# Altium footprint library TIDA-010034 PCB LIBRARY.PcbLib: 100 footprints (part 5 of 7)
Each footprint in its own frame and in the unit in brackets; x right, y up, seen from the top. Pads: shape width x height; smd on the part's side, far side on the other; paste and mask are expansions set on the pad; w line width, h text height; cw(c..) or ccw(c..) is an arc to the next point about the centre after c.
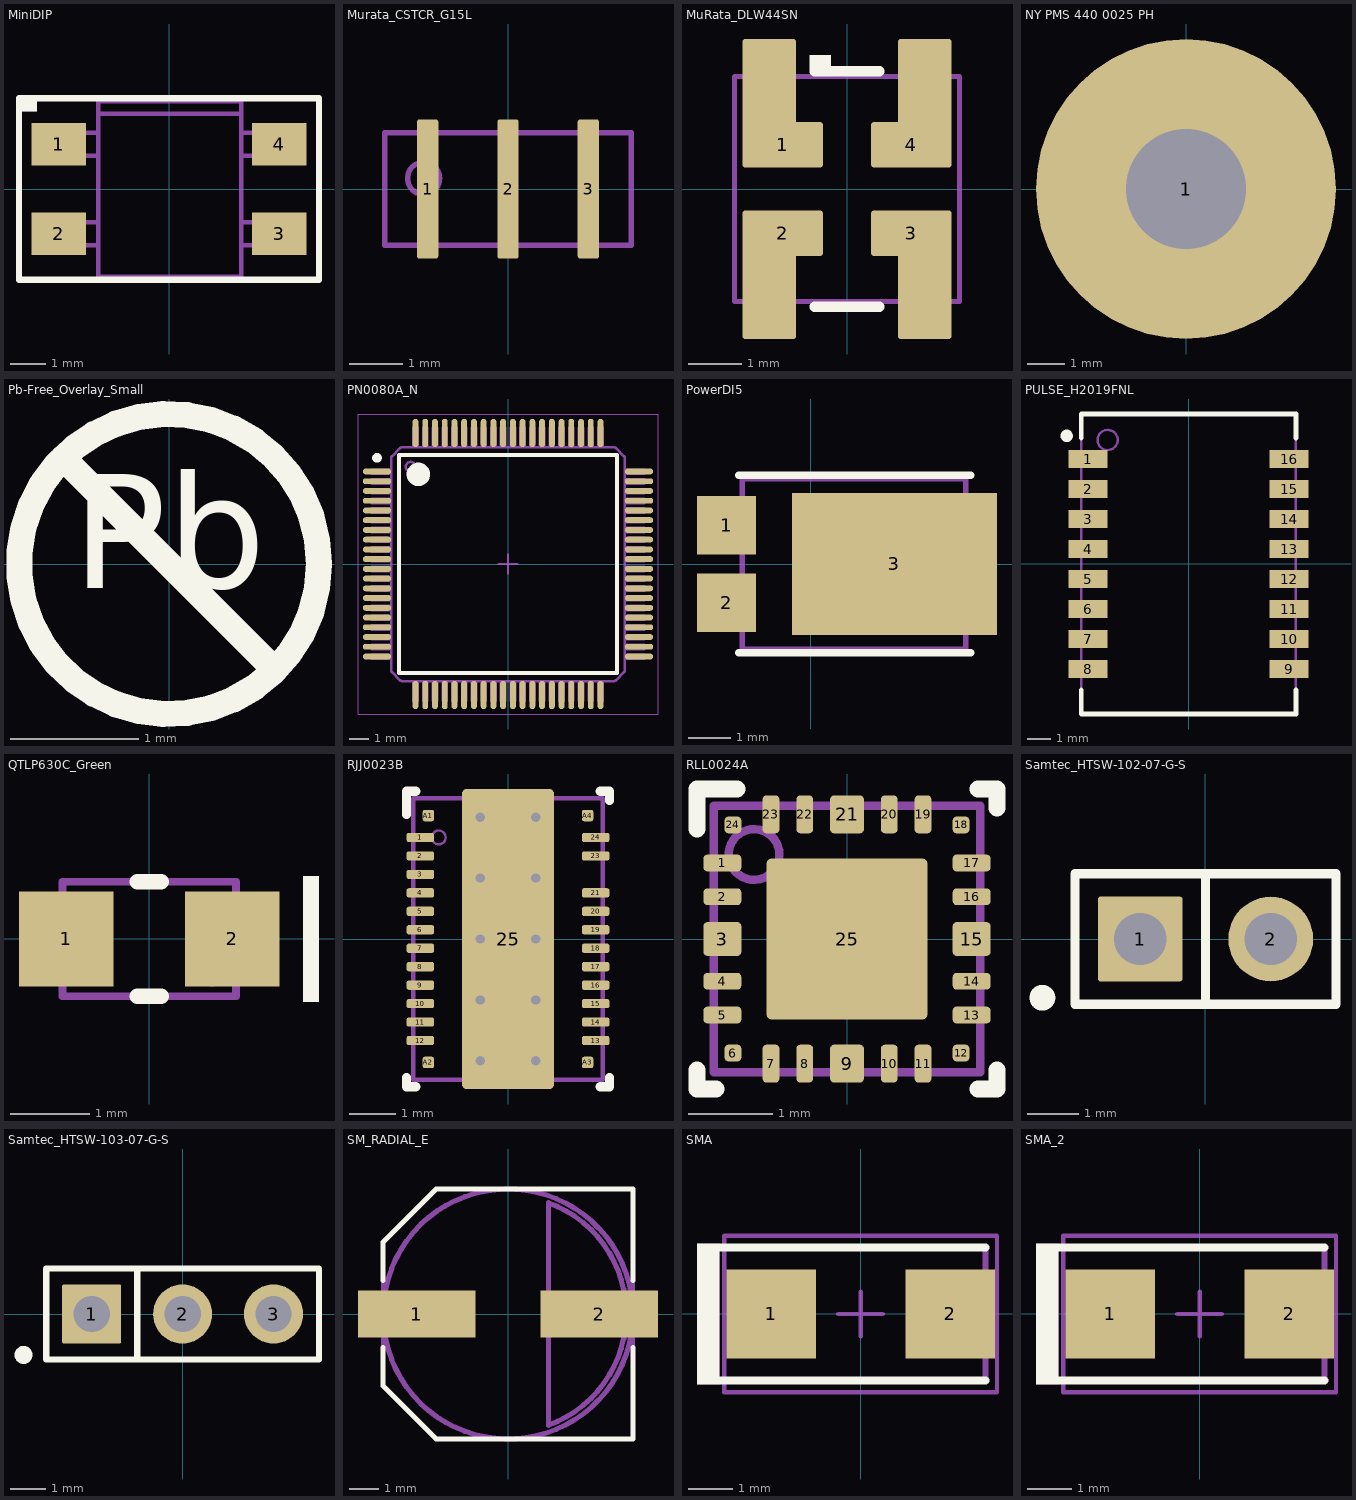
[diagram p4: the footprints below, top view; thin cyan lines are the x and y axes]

## MiniDIP [mm] "Land pattern created based on STEP model."
height 2.7
pads (4):
  rect 1.52x1.2 smd: 1(-3.075,1.25) 2(-3.075,-1.25) 3(3.075,-1.25) 4(3.075,1.25)
Top Overlay:
  rectangle: -4.191,2.159 -3.683,2.54
  lines w0.178: -4.191,-2.54 0,-2.54 4.191,-2.54 4.191,0 4.191,2.54 0,2.54 -4.191,2.54 -4.191,0 -4.191,-2.54
Mechanical 5:
  rectangle: -4.191,2.159 -3.683,2.54
  lines w0.127: -1.975,-1.575 -2.825,-1.575 ; -1.975,-0.925 -2.825,-0.925 ; -1.975,0.925 -2.825,0.925 ; -1.975,1.575 -2.825,1.575 ; 2.025,-1.575 2.875,-1.575 ; 2.025,-0.925 2.875,-0.925 ; 2.025,0.925 2.875,0.925 ; 2.025,1.575 2.875,1.575 ; -2.825,-1.575 -2.825,-0.925 ; -2.825,-1.575 -3.475,-1.575 -3.475,-0.925 -2.825,-0.925 ; -2.825,0.925 -3.475,0.925 -3.475,1.575 -2.825,1.575 ; -2.825,0.925 -2.825,1.575 ; -1.975,2.1 2.025,2.1 ; -1.975,2.1 -1.975,2.45 2.025,2.45 2.025,2.1 ; -1.975,2.1 -1.975,-2.45 2.025,-2.45 2.025,2.1 ; 2.875,-1.575 3.525,-1.575 3.525,-0.925 2.875,-0.925 ; 2.875,-1.575 2.875,-0.925 ; 2.875,0.925 3.525,0.925 3.525,1.575 2.875,1.575 ; 2.875,0.925 2.875,1.575
  text ".Designator" at -1.675,-0.25 h0.76
3D body "Minidip.stp": height 2.75, standoff 0, extent -3.5,-2.45 3.5,2.45

## Murata_CSTCR_G15L [mm] "Murata"
height 1.15
pads (3):
  rrect25% 0.4x2.6 smd: 1(-1.5,0) 2(0,0) 3(1.5,0)
Mechanical 5:
  circle w0.1: c-1.575,0.2 r0.3
  lines w0.1: -2.3,-1.05 -2.3,1.05 2.3,1.05 2.3,-1.05 -2.3,-1.05
  text ".Designator" at -0.95,-0.325 h0.51
3D body: height 0.6, standoff 0, extent -2.299,-1.049 2.299,1.051
3D body: height 1.2, standoff 0.6, extent -2,-0.875 2,0.875

## MuRata_DLW44SN [mm] "SMD, 4-Leads, Body 4.2x4.2mm"
height 1.5
pads (8):
  rrect12% 1.5x0.85 smd: 1(-1.2,0.825) 2(-1.2,-0.825) 3(1.2,-0.825) 4(1.2,0.825)
  rrect10% 1x2.4 smd: ""(-1.45,-1.6) ""(-1.45,1.6) ""(1.45,-1.6) ""(1.45,1.6)
Top Overlay:
  rectangle: -0.7,2.2 -0.3,2.5
  lines w0.2: -0.6,-2.2 0.6,-2.2 ; -0.6,2.2 0.6,2.2
Mechanical 5:
  circle w0.1: c-1.5,1.4 r0.361
  lines w0.1: -2.1,-2.1 2.1,-2.1 2.1,2.1 -2.1,2.1 -2.1,-2.1
  text ".Designator" at -1.4,-0.3 h0.8
3D body: height 1.5, standoff 0, extent -2.1,-2.1 2.1,2.1
3D body: height 1.5, standoff 1.5, extent -1.86,1.04 -1.14,1.76

## NY PMS 440 0025 PH [mm] "4-40 nylon screw and mounting hole"
height 1.905
pads (1):
  round 8 hole 3.2: 1(0,0)
Mechanical 5:
  circle w0.127: c0,0 r3.789
  text ".Designator" at -1.524,-0.508 h1.02
3D body "B_F_NY PMS 440 0025 PH.stp": height 2.69, standoff -8.74, extent -3.302,-3.3 3.296,3.3

## Pb-Free_Overlay_Small [mm]
Top Overlay:
  circle w0.203: c0,0 r1.168
  lines w0.203: -0.826,0.826 0.826,-0.826
  text "Pb" at -0.752,-0.48 h1.52

## PN0080A_N [mm] "QFP, 80-Leads, Body 12x12mm, Pitch 0.5mm, IPC Medium Density"
height 1.6
pads (80):
  oval 1.45x0.3 smd: 1(-6.725,4.75) 2(-6.725,4.25) 3(-6.725,3.75) 4(-6.725,3.25) 5(-6.725,2.75) 6(-6.725,2.25) 7(-6.725,1.75) 8(-6.725,1.25) 9(-6.725,0.75) 10(-6.725,0.25) 11(-6.725,-0.25) 12(-6.725,-0.75) 13(-6.725,-1.25) 14(-6.725,-1.75) 15(-6.725,-2.25) 16(-6.725,-2.75) 17(-6.725,-3.25) 18(-6.725,-3.75) 19(-6.725,-4.25) 20(-6.725,-4.75) 41(6.725,-4.75) 42(6.725,-4.25) 43(6.725,-3.75) 44(6.725,-3.25) 45(6.725,-2.75) 46(6.725,-2.25) 47(6.725,-1.75) 48(6.725,-1.25) 49(6.725,-0.75) 50(6.725,-0.25) 51(6.725,0.25) 52(6.725,0.75) 53(6.725,1.25) 54(6.725,1.75) 55(6.725,2.25) 56(6.725,2.75) 57(6.725,3.25) 58(6.725,3.75) 59(6.725,4.25) 60(6.725,4.75)
  oval 0.3x1.45 smd: 21(-4.75,-6.725) 22(-4.25,-6.725) 23(-3.75,-6.725) 24(-3.25,-6.725) 25(-2.75,-6.725) 26(-2.25,-6.725) 27(-1.75,-6.725) 28(-1.25,-6.725) 29(-0.75,-6.725) 30(-0.25,-6.725) 31(0.25,-6.725) 32(0.75,-6.725) 33(1.25,-6.725) 34(1.75,-6.725) 35(2.25,-6.725) 36(2.75,-6.725) 37(3.25,-6.725) 38(3.75,-6.725) 39(4.25,-6.725) 40(4.75,-6.725) 61(4.75,6.725) 62(4.25,6.725) 63(3.75,6.725) 64(3.25,6.725) 65(2.75,6.725) 66(2.25,6.725) 67(1.75,6.725) 68(1.25,6.725) 69(0.75,6.725) 70(0.25,6.725) 71(-0.25,6.725) 72(-0.75,6.725) 73(-1.25,6.725) 74(-1.75,6.725) 75(-2.25,6.725) 76(-2.75,6.725) 77(-3.25,6.725) 78(-3.75,6.725) 79(-4.25,6.725) 80(-4.75,6.725)
Top Overlay:
  circle w0.6: c-4.6,4.6 r0.3
  circle w0.25: c-6.725,5.45 r0.125
  lines w0.2: -5.6,-5.6 5.6,-5.6 5.6,5.6 -5.6,5.6 -5.6,-5.6
Mechanical 5:
  drawing of 978 lines, arcs and shapes, not listed
  text ".Designator" at -1.825,-0.5 h1.02
Mechanical 15:
  lines w0.05: -7.7,-7.7 7.7,-7.7 7.7,7.7 -7.7,7.7 -7.7,-7.7
  lines w0.1: -0.5,0 0.5,0 ; 0,-0.5 0,0.5
3D body "PN0080A.stp": height 1.56, standoff 0, extent -7,-7 7,7

## PowerDI5 [mm] "Diodes Inc recommended land pattern, ap02001.pdf rev 60"
height 1.15
pads (3):
  rect 1.4x1.39 smd: 1(-1.991,0.92) 2(-1.991,-0.92)
  rect 4.86x3.36 smd: 3(1.991,0)
Top Overlay:
  lines w0.18: -1.7,-2.1 3.8,-2.1 ; -1.7,2.1 3.8,2.1
Mechanical 5:
  lines w0.127: -1.619,-1.415 -2.269,-1.415 -2.269,-0.425 -1.619,-0.425 ; -1.619,-1.415 -1.619,-2.025 3.681,-2.025 3.681,-0.94 ; -1.619,-1.415 -1.619,-0.425 ; -1.619,-0.425 -1.619,0.425 ; -1.619,0.425 -2.269,0.425 -2.269,1.415 -1.619,1.415 ; -1.619,0.425 -1.619,1.415 ; -1.619,1.415 -1.619,2.025 3.681,2.025 3.681,0.94 ; 3.681,-0.94 4.331,-0.94 4.331,-0.5 4.181,-0.5 4.181,0.5 4.331,0.5 4.331,0.94 3.681,0.94 ; 3.681,-0.94 3.681,0.94
  text ".Designator" at -1.319,-0.4 h1.02
3D body "PowerDI-5.stp": height 1.17, standoff 0.02, extent -2.269,-2.025 4.331,2.025

## PULSE_H2019FNL [mil] "PULSE"
height 236
pads (16):
  rect 65x30 smd paste+0: 1(-167.51,174.99) 2(-167.51,124.99) 3(-167.51,74.99) 4(-167.51,24.99) 5(-167.51,-25.01) 6(-167.51,-75.01) 7(-167.51,-125.01) 8(-167.51,-175.01) 9(167.49,-175.01) 10(167.49,-125.01) 11(167.49,-75.01) 12(167.49,-25.01) 13(167.49,24.99) 14(167.49,74.99) 15(167.49,124.99) 16(167.49,174.99)
Top Overlay:
  circle w10: c-203.13,213.58 r5.3
  lines w7.87: -179,-210 -179.01,-250.01 178.99,-250.01 179,-210 ; -179,210 -179.01,249.99 178.99,249.99 179,210
Mechanical 5:
  circle w3.94: c-134.84,206.69 r16.82
  lines w3.94: -179.01,-250.01 178.99,-250.01 178.99,249.99 -179.01,249.99 -179.01,-250.01
  text ".Designator" at -67.91,-12.8 h40
3D body: height 236, standoff 0, extent -178.99,-249.99 178.97,249.97
3D body: height 236.39, standoff 236, extent -146.56,194.91 -123.03,218.49

## QTLP630C_Green [mm] "SMT, 2-Leads, Body 2x1.25mm"
height 1.2
pads (2):
  rect 1.2x1.2 smd: 1(-1.05,0) 2(1.05,0)
Top Overlay:
  region: 2.15,0.8 1.95,0.8 1.95,-0.8 2.15,-0.8
  lines w0.2: -0.15,-0.725 0.15,-0.725 ; -0.15,0.725 0.15,0.725
Mechanical 5:
  circle w0.1: c0.8,-0.4 r0.15
  lines w0.1: -1.1,-0.725 1.1,-0.725 1.1,-0.2 cw(c1.1,0) 1.1,0.2 1.1,0.725 -1.1,0.725 -1.1,0.2 cw(c-1.1,0) -1.1,-0.2 -1.1,-0.725
  text ".Designator" at -0.8,-0.1 h0.45
3D body: height 1.2, standoff 0.6, extent -0.7,-0.725 0.7,0.725
3D body: height 1.22, standoff 1.2, extent 0.3,0.3 0.7,0.725
3D body: height 1.22, standoff 1.2, extent 0.3,-0.725 0.7,-0.3
3D body: height 0.6, standoff 0, extent -1.101,-0.726 1.101,0.726

## RJJ0023B [mm] "SMD, 23-Leads, Body 4x6mm"
height 1
pads (46):
  rrect50% 0.6x0.2 smd: 1(-1.9,2.2) 2(-1.9,1.8) 3(-1.9,1.4) 4(-1.9,1) 5(-1.9,0.6) 6(-1.9,0.2) 7(-1.9,-0.2) 8(-1.9,-0.6) 9(-1.9,-1) 10(-1.9,-1.4) 11(-1.9,-1.8) 12(-1.9,-2.2) 13(1.9,-2.2) 14(1.9,-1.8) 15(1.9,-1.4) 16(1.9,-1) 17(1.9,-0.6) 18(1.9,-0.2) 19(1.9,0.2) 20(1.9,0.6) 21(1.9,1) 23(1.9,1.8) 24(1.9,2.2)
  rrect10% 2x6.5 smd paste-2 mask-2: 25(0,0)
  rrect40% 0.25x0.25 smd: A1(-1.725,2.675) A2(-1.725,-2.675) A3(1.725,-2.675) A4(1.725,2.675)
  rrect50% 0.2x0.46 on Top Paste: ""(-0.8,-2.97) ""(-0.8,2.97) ""(-0.4,-2.97) ""(-0.4,2.97) ""(0,-2.97) ""(0,2.97) ""(0.4,-2.97) ""(0.4,2.97) ""(0.8,-2.97) ""(0.8,2.97)
  rrect50% 0.85x1.12 on Top Paste: ""(-0.525,-1.98) ""(-0.525,-0.66) ""(-0.525,0.66) ""(-0.525,1.98) ""(0.525,-1.98) ""(0.525,-0.66) ""(0.525,0.66) ""(0.525,1.98)
via 0.6,-2.64 diameter 0.5 hole 0.2
via -0.6,-2.64 diameter 0.5 hole 0.2
via 0.6,-1.32 diameter 0.5 hole 0.2
via -0.6,-1.32 diameter 0.5 hole 0.2
via 0.6,2.64 diameter 0.5 hole 0.2
via -0.6,2.64 diameter 0.5 hole 0.2
via 0.6,1.32 diameter 0.5 hole 0.2
via -0.6,1.32 diameter 0.5 hole 0.2
via -0.6,0 diameter 0.5 hole 0.2
via 0.6,0 diameter 0.5 hole 0.2
Top Overlay:
  lines w0.2: -2.2,-3 -2.2,-3.2 -2,-3.2 ; -2.2,2.7 -2.2,3.2 -2,3.2 ; 2,-3.2 2.2,-3.2 2.2,-3 ; 2,3.2 2.2,3.2 2.2,3
Top Solder:
  drawing of 1 lines, arcs and shapes, not listed
Mechanical 5:
  circle w0.05: c-1.5,2.2 r0.15
  lines w0.1: -2.05,-3.05 -2.05,3.05 2.05,3.05 2.05,-3.05 -2.05,-3.05
  text ".Designator" at -0.804,5.205 h1.02
3D body "RJJ0023B.stp": height 1, standoff 0, extent -2,-3 2,3

## RLL0024A [mm] "QFN, 24-Leads, Body 3x3mm"
height 1
pads (26):
  rrect50% 0.45x0.2 smd: 1(-1.475,0.9) 2(-1.475,0.5) 4(-1.475,-0.5) 5(-1.475,-0.9) 13(1.475,-0.9) 14(1.475,-0.5) 16(1.475,0.5) 17(1.475,0.9)
  rrect25% 0.45x0.4 smd: 3(-1.475,0) 15(1.475,0)
  rrect50% 0.2x0.2 smd: 6(-1.35,-1.35) 12(1.35,-1.35) 18(1.35,1.35) 24(-1.35,1.35)
  rrect50% 0.2x0.45 smd: 7(-0.9,-1.475) 8(-0.5,-1.475) 10(0.5,-1.475) 11(0.9,-1.475) 19(0.9,1.475) 20(0.5,1.475) 22(-0.5,1.475) 23(-0.9,1.475)
  rrect25% 0.4x0.45 smd: 9(0,-1.475) 21(0,1.475)
  rrect5% 1.9x1.9 smd paste-1.9: 25(0,0)
  rrect50% 1.71x1.71 on Top Paste: ""(0,0)
Top Overlay:
  lines w0.2: -1.775,-1.55 -1.775,-1.775 -1.55,-1.775 ; -1.775,1.3 -1.775,1.775 -1.3,1.775 ; 1.55,-1.775 1.775,-1.775 1.775,-1.55 ; 1.55,1.775 1.775,1.775 1.775,1.55
Mechanical 5:
  circle w0.1: c-1.1,1 r0.3
  lines w0.1: -1.575,-1.575 1.575,-1.575 1.575,1.575 -1.575,1.575 -1.575,-1.575
  text ".Designator" at -3.9,-0.7 h0.75
3D body: height 1, standoff 0.08, extent -1.575,-1.575 1.575,1.575
3D body: height 1.01, standoff 1, extent -1.399,0.701 -0.801,1.299

## Samtec_HTSW-102-07-G-S [mm] "Samtec 100mil, 1x2, 230 mil above insulator"
height 8.382
pads (2):
  rrect6% 1.65x1.65 hole 1.016: 1(-1.27,0)
  round 1.65 hole 1.016: 2(1.27,0)
Top Overlay:
  circle w0.25: c-3.173,-1.143 r0.125
  lines w0.178: 0,-1.27 0,1.27 ; -2.54,-1.27 2.54,-1.27 2.54,1.27 -2.54,1.27 -2.54,-1.27
Mechanical 5:
  lines w0.127: -2.54,-1.27 -2.54,1.27 2.54,1.27 2.54,-1.27 -2.54,-1.27
  text ".Designator" at -1.524,-0.508 h0.86
3D body: height 2.54, standoff 0, extent -2.539,-1.269 2.539,1.269
3D body: height 8.38, standoff -2.03, extent -1.587,-0.317 -0.953,0.317
3D body: height 8.38, standoff -2.03, extent 0.953,-0.317 1.587,0.317

## Samtec_HTSW-103-07-G-S [mm] "Samtec 100mil, 1x3, 230 mil above insulator"
height 8.382
pads (3):
  rrect6% 1.65x1.65 hole 1.016: 1(-2.54,0)
  round 1.65 hole 1.016: 2(0,0) 3(2.54,0)
Top Overlay:
  circle w0.25: c-4.443,-1.143 r0.125
  lines w0.178: -1.27,-1.27 -1.27,1.27 ; -3.81,-1.27 3.81,-1.27 3.81,1.27 -3.81,1.27 -3.81,-1.27
Mechanical 5:
  rectangle: -3.048,-0.508 -2.032,0.508
  lines w0.127: -3.81,-1.27 -3.81,1.27 3.81,1.27 3.81,-1.27 -3.81,-1.27
  text ".Designator" at -1.016,-0.635 h1.02
3D body: height 8.38, standoff -2.03, extent -2.857,-0.317 -2.223,0.317
3D body: height 8.38, standoff -2.03, extent -0.317,-0.317 0.317,0.317
3D body: height 8.38, standoff -2.03, extent 2.223,-0.317 2.857,0.317
3D body: height 2.54, standoff 0, extent -3.809,-1.269 3.809,1.269

## SM_RADIAL_E [mm] "8 x 6.2mm:  Panasonic E"
height 6.5
pads (2):
  rect 4x1.6 smd: 1(-3.1,0) 2(3.1,0)
Top Overlay:
  lines w0.178: -4.25,-1.15 -4.25,-2.44 -2.44,-4.25 0,-4.25 4.25,-4.25 4.25,-1.15 ; -4.25,1.15 -4.25,2.44 -2.44,4.25 0,4.25 4.25,4.25 4.25,1.15
Mechanical 5:
  lines w0.127: -4.25,-2.44 -2.44,-4.25 0,-4.25 4.25,-4.25 4.25,4.25 0,4.25 -2.44,4.25 -4.25,2.44 -4.25,-2.44
  text ".Designator" at -1.524,-0.508 h1.02
Mechanical 13:
  circle w0.178: c0,0 r4.25
  lines w0.178: 1.376,-3.779 ccw(c0,0) 1.376,3.779 1.376,-3.779
3D body: height 0.6, standoff 0, extent -4.251,-4.251 4.251,4.251
3D body: height 6.5, standoff 0.6, extent -4.249,-4.249 4.249,4.249
3D body: height 6.5, standoff 6.4, extent 1.375,-3.78 4.022,3.78

## SMA [mm] "Molded Diode, 2-Leads, Body 4.3x2.6mm, IPC Medium Density, based on OnSemi component dimensions and land pattern"
height 2.27
pads (2):
  rect 2x2 smd: 1(-2,0) 2(2,0)
Top Overlay:
  rectangle: -3.658,-1.575 -3.15,1.575
  lines w0.178: -3.327,-1.486 2.794,-1.486 ; -3.327,1.486 2.794,1.486
Mechanical 5:
  rectangle: -3.658,-1.575 -3.15,1.575
  lines w0.127: -3.327,-1.486 2.794,-1.486 2.794,1.486 -3.327,1.486
  text ".Designator" at -2.769,-0.33 h1.02
Mechanical 15:
  lines w0.1: -0.5,0 0.5,0 ; 0,-0.5 0,0.5 ; -3.05,-1.75 3.05,-1.75 3.05,1.75 -3.05,1.75 -3.05,-1.75
3D body "SMA_nominal.stp": height 2.42, standoff 0.02, extent -2.6,-1.3 2.6,1.3

## SMA_2 [mm]
pads (2):
  rect 2x2 smd: 1(-2,0) 2(2,0)
Top Overlay:
  rectangle: -3.658,-1.575 -3.15,1.575
  lines w0.178: -3.327,-1.486 2.794,-1.486 ; -3.327,1.486 2.794,1.486
Mechanical 5:
  rectangle: -3.658,-1.575 -3.15,1.575
  lines w0.127: -3.327,-1.486 2.794,-1.486 2.794,1.486 -3.327,1.486
  text ".Designator" at -2.769,-0.33 h1.02
Mechanical 15:
  lines w0.1: -0.5,0 0.5,0 ; 0,-0.5 0,0.5 ; -3.05,-1.75 3.05,-1.75 3.05,1.75 -3.05,1.75 -3.05,-1.75
3D body "SMA_nominal.stp": height 2.42, standoff 0.02, extent -2.6,-1.3 2.6,1.3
